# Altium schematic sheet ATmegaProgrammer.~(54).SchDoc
size A4
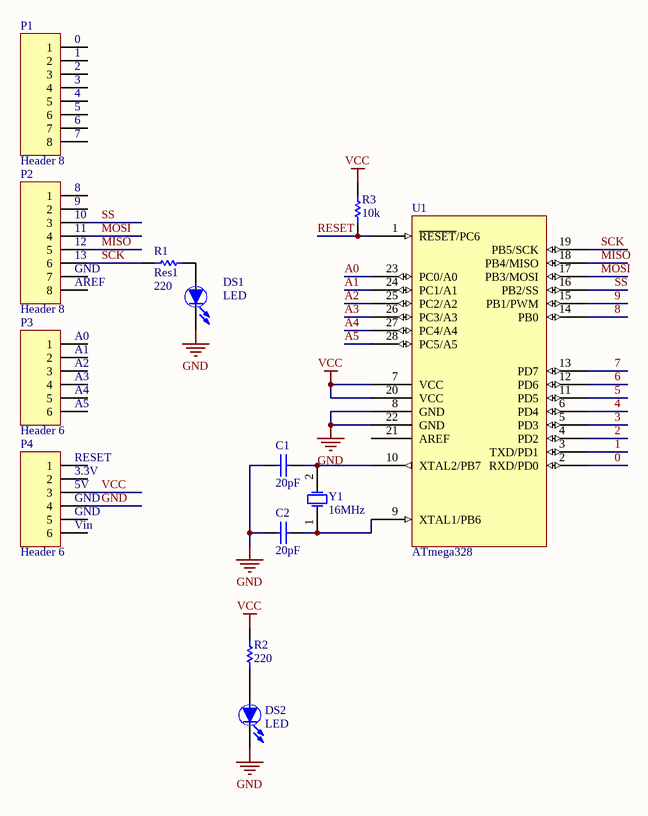
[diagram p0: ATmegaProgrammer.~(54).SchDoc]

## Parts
C1  20pF  [C200]
C2  20pF  [C200]
DS1  LED  [LED-3mm_G]
DS2  LED  [LED-3mm_G]
P1  Header 8  [HDR1X8]
P2  Header 8  [HDR1X8]
P3  Header 6  [HDR1X6]
P4  Header 6  [HDR1X6]
R1  Res1  value 220  [AXIAL-0.3]
R2  220  [AXIAL-0.3]
R3  10k  [AXIAL-0.3]
U1  ATmega328  [DIP-28]
Y1  16MHz  [XTAL4-8]

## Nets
GND: C1.1 C2.1 DS1.2(K) DS2.2(K) P4.4 U1.8(GND) U1.22(GND)
VCC: P4.3 R2.2 R3.2 U1.7(VCC) U1.20(VCC)
0: U1.2(RXD/PD0)
1: U1.3(TXD/PD1)
2: U1.4(PD2)
3: U1.5(PD3)
4: U1.6(PD4)
5: U1.11(PD5)
6: U1.12(PD6)
7: U1.13(PD7)
8: U1.14(PB0)
9: U1.15(PB1/PWM)
A0: U1.23(PC0/A0)
A1: U1.24(PC1/A1)
A2: U1.25(PC2/A2)
A3: U1.26(PC3/A3)
A4: U1.27(PC4/A4)
A5: U1.28(PC5/A5)
MISO: P2.5 U1.18(PB4/MISO)
MOSI: P2.4 U1.17(PB3/MOSI)
RESET: R3.1 U1.1(~{RESET}/PC6)
SCK: P2.6 R1.2 U1.19(PB5/SCK)
SS: P2.3 U1.16(PB2/SS)
NetC1_2: C1.2 U1.10(XTAL2/PB7) Y1.2(OSC2)
NetC2_2: C2.2 U1.9(XTAL1/PB6) Y1.1(OSC1)
NetDS1_1: DS1.1(A) R1.1
NetDS2_1: DS2.1(A) R2.1

Not connected (* = marked no-connect by the designer): P1 1 2 3 4 5 6 7 8; P2 1 2 7 8; P3 1 2 3 4 5 6; P4 1 2 5 6; U1 21(AREF)

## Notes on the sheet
- (near P1) 0
- (near P1) 1
- (near P1) 2
- (near P1) 3
- (near P1) 4
- (near P1) 5
- (near P1) 6
- (near P1) 7
- (near P2) 8
- (near P2) 9
- (near P2) 10
- (near P2) 11
- (near P2) 12
- (near P2) 13
- (near P2) GND
- (near P2) AREF
- (near P3) A0
- (near P3) A1
- (near P3) A2
- (near P3) A3
- (near P3) A4
- (near P3) A5
- (near P4) RESET
- (near P4) 3.3V
- (near P4) 5V
- (near P4) GND
- (near P4) Vin

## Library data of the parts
C1 C2 = Cap: Capacitor
DS1 DS2 = LED: Typical INFRARED GaAs LED
P1 P2 = Header 8: Header, 8-Pin
P3 P4 = Header 6: Header, 6-Pin
R1 = Res1: Resistor
R2 R3 = Res: Resistor
U1 = ATmega328: Arduino
Y1 = XTAL: Crystal Oscillator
